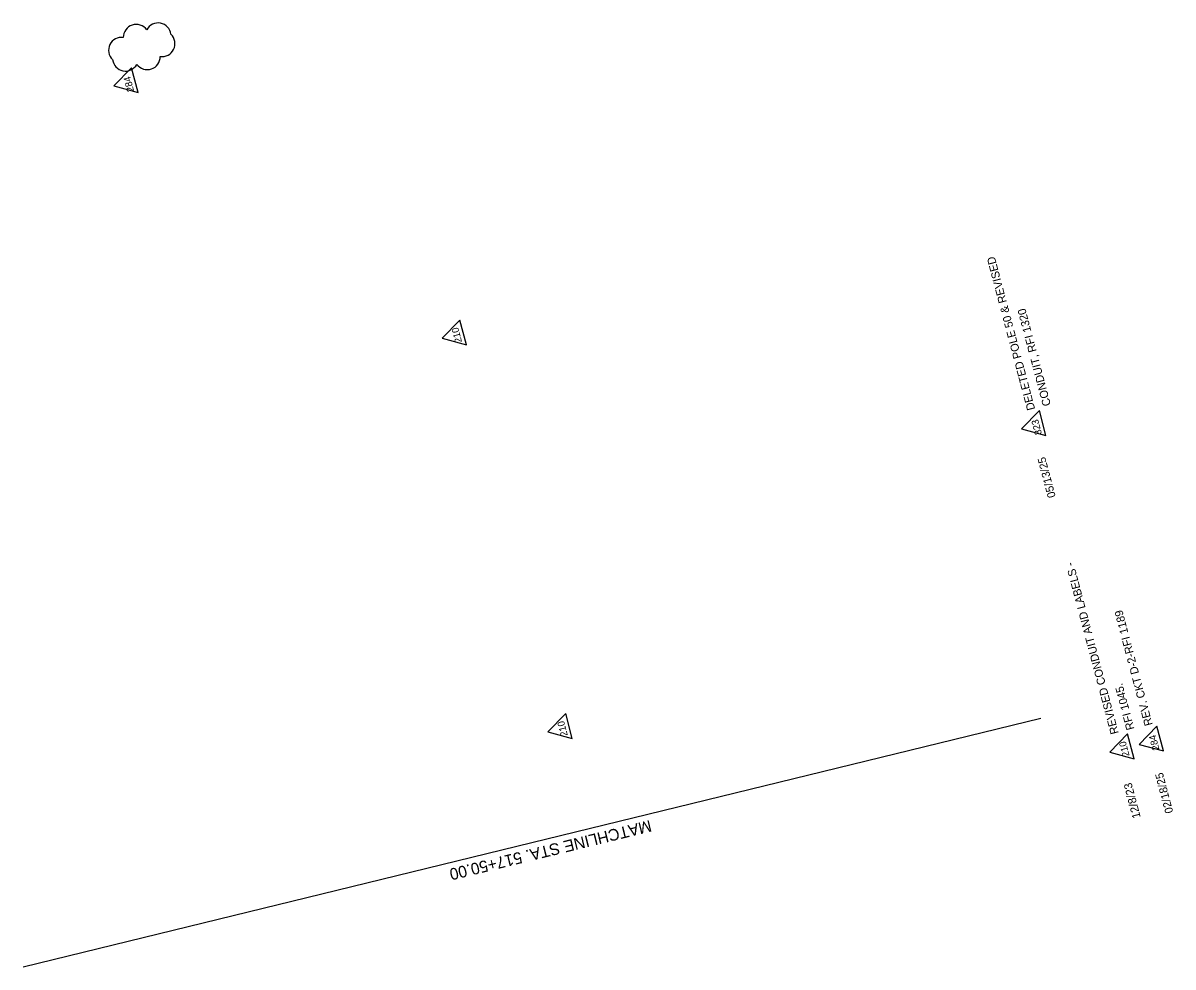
# Model space of a CAD drawing. Extents: x 930394 to 931451, y 627795 to 629076.
# Drawn here: x 930661 to 931451, y 627795 to 628444 of the extents above; entities that cross this region are included whole.
import ezdxf

# ---------------------------------------------------------------- set-up
doc = ezdxf.new("R2010")
doc.units = 0
for name, color, linetype in [('Cloud_dp', 7, 'Continuous'), ('MatchLines_dp', 7, 'Continuous'), ('TextMinor', 7, 'Continuous')]:
    doc.layers.add(name, color=color, linetype=linetype)

msp = doc.modelspace()

# ---------------------------------------------------------------- linework, layer by layer
at = {"layer": 'Cloud_dp'}
for points in [[(930723.2, 628400.44), (930739.95, 628395.96), (930735.43, 628413.02)], [(930948.85, 628226.94), (930965.6, 628222.46), (930961.08, 628239.52)], [(931347.08, 628164.68), (931363.83, 628160.2), (931359.32, 628177.26)], [(931021.55, 627956.33), (931038.3, 627951.84), (931033.78, 627968.91)], [(931427.85, 627947.72), (931444.6, 627943.24), (931440.08, 627960.3)], [(931407.6, 627942.36), (931424.35, 627937.88), (931419.83, 627954.94)]]:
    msp.add_lwpolyline(points, close=True, dxfattribs=at)
for centre, radius, start, end in [((930738.61, 628433.89), 8.88, 35.6123, 180.6123), ((930753.66, 628434.89), 8.87, 6.944, 151.944), ((930728.47, 628425.01), 8.87, 81.77379, 226.77379), ((930756.35, 628429.53), 8.88, 261.46323, 46.46323), ((930731.21, 628419.54), 8.88, 186.40976, 331.40976), ((930746.16, 628420.55), 8.88, 216.30499, 1.30499)]:
    msp.add_arc(centre, radius, start, end, dxfattribs=at)
at = {"layer": 'MatchLines_dp'}
msp.add_lwpolyline([(931360.22, 627965.54), (931010.5, 627880.11), (930660.79, 627794.67)], dxfattribs=at)

# ---------------------------------------------------------------- texts
at = {"layer": 'Cloud_dp'}
for s, p in [('284', (930737.16, 628397.07)), ('210', (930962.56, 628224.51)), ('323', (931361.08, 628161.2)), ('210', (931035.26, 627953.9)), ('210', (931421.31, 627939.93)), ('284', (931441.81, 627944.35))]:
    msp.add_text(s, height=4.799, rotation=104.82565, dxfattribs=at).set_placement(p)
at = {"layer": 'MatchLines_dp'}
msp.add_text('MATCHLINE STA. 517+50.00', height=8, rotation=193.7289, dxfattribs=at).set_placement((931091.6, 627895.8))
at = {"layer": 'TextMinor'}
for s, height, p in [('DELETED POLE 50 & REVISED ', 5.6, (931356.43, 628178.26)), ('CONDUIT, RFI 1320', 5.6, (931367.26, 628181.13)), ('05/13/25', 5.5, (931370.57, 628118.1)), ('REVISED CONDUIT AND LABELS - ', 5.6, (931413.85, 627955.53)), ('REV. CKT D-2-RFI 1189', 5.6, (931437.19, 627961.31)), ('RFI 1045.', 5.6, (931424.68, 627958.4)), ('02/18/25', 5.5, (931451.34, 627901.11)), ('12/8/23', 5.6, (931428.97, 627897.64))]:
    msp.add_text(s, height=height, rotation=104.82565, dxfattribs=at).set_placement(p)

doc.saveas('drawing.dxf')
